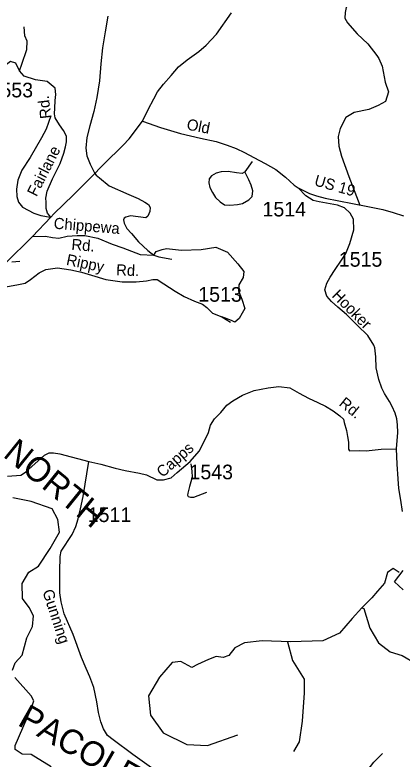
# Model space of a CAD drawing. Extents: x 990631 to 1056237, y 535999 to 585651.
# Drawn here: x 1035882 to 1039191, y 551047 to 557410 of the extents above; entities that cross this region are included whole.
import ezdxf

# ---------------------------------------------------------------- set-up
doc = ezdxf.new("R2010")
doc.units = 0
for name, color, linetype in [('Exist Hydrographic River Shore', 7, 'Continuous'), ('Exist Hydrographic River Shore Label', 7, 'Continuous'), ('Exist Road Non-System Type 51', 7, 'Continuous'), ('Exist Road Non-System Type 51 Label', 7, 'Continuous'), ('Exist Road Primary NC Attributed', 7, 'Continuous'), ('Exist Road Primary NC Structure Standard Bridge CELL', 7, 'Continuous'), ('Exist Road Secondary Type 41 Attributed', 7, 'Continuous'), ('Exist Road Secondary Type 51 Attributed', 7, 'Continuous'), ('Exist Road Secondary Type 51 Label', 7, 'Continuous'), ('Exist Road Secondary Type 51 Number Label', 7, 'Continuous')]:
    doc.layers.add(name, color=color, linetype=linetype)

msp = doc.modelspace()

# ---------------------------------------------------------------- linework, layer by layer
at = {"layer": 'Exist Hydrographic River Shore'}
for points in [[(1035860.8, 551807.2), (1035884.8, 551871.3), (1035944.8, 551935.4), (1035984.8, 552083.6), (1036032.9, 552179.7), (1036040.9, 552271.8), (1036004.9, 552343.9), (1035948.8, 552420.1), (1035944.8, 552548.2), (1036000.9, 552644.4), (1036084.9, 552696.4), (1036185, 552848.7), (1036265, 552988.9), (1036249, 553095), (1036201, 553187.1), (1036020.9, 553251.2), (1035865.5, 553280)], [(1036192.2, 550982.6), (1036020.9, 551085.9), (1035944.8, 551089.9), (1035884.8, 551129.9), (1035884.8, 551164.4), (1036024.9, 551484.8), (1036044.9, 551544.9), (1036020.9, 551589), (1035880.8, 551745.2)]]:
    msp.add_lwpolyline(points, dxfattribs=at)
at = {"layer": 'Exist Road Non-System Type 51'}
msp.add_line((1037908.7, 556156.4), (1037847.7, 556068.2), dxfattribs=at)
for points in [[(1038865.7, 557977), (1038864.4, 557873), (1038839.2, 557711.6), (1038821.1, 557648.2), (1038747.3, 557532.4), (1038713.5, 557473.5), (1038706.1, 557431.8), (1038702.5, 557381.9), (1038723.3, 557343), (1038808.2, 557248.3), (1038899.5, 557163.4), (1038974.3, 557062.9), (1038991.6, 557036.3), (1039021.5, 556971.3), (1039045.2, 556834.4)], [(1036677.7, 557398.6), (1036653.4, 557265.3), (1036631.1, 557128.1), (1036616.5, 556992.3), (1036606, 556846.7), (1036581.3, 556705.3), (1036557.5, 556583.9), (1036521.6, 556461), (1036496.4, 556361.7), (1036489.3, 556270), (1036497.2, 556205.6), (1036527, 556134.6), (1036566.4, 556053.4), (1036578.1, 556040.9)], [(1036232.8, 556730), (1036226.2, 556784.9), (1036159.3, 556839.3), (1036059, 556856), (1035962.9, 556885.3), (1035921.1, 556931.3), (1035942, 556989.9), (1035983.8, 557115.3), (1035987.9, 557186.4), (1035967, 557232.4), (1035962.9, 557307.7)], [(1035921.1, 556931.3), (1035891.8, 556998.2), (1035845.8, 557010.8), (1035799.8, 556977.3), (1035749.7, 556922.9), (1035695.3, 556835.1), (1035661.9, 556730.6)], [(1039045.2, 556834.4), (1039073.6, 556752.2), (1039048.5, 556668.6), (1038985.8, 556635.1), (1038906.4, 556601.7), (1038781, 556576.6), (1038709.6, 556533), (1038661.4, 556438.5), (1038646.1, 556370.8), (1038649.4, 556286.7), (1038672.7, 556202), (1038737, 556029.7), (1038829.1, 555784.8)], [(1036190, 556547.7), (1036148.3, 556432.9), (1036110, 556358.3), (1036012.6, 556191.2), (1035943, 556083.3), (1035908.2, 555996.4), (1035895.9, 555920.8), (1035897.8, 555856.6), (1035912.3, 555810.1), (1035948.8, 555766.9), (1036043.2, 555714), (1036104.6, 555695.9), (1036186.3, 555680.1)], [(1037847.7, 556068.2), (1037845.7, 556066.4), (1037825.2, 556053), (1037777.5, 556060.6), (1037703.7, 556070.9), (1037645.7, 556068.9), (1037601.2, 556058.1), (1037562.6, 556035.3), (1037543.6, 556008.1), (1037540.5, 555974.1), (1037549.3, 555933.7), (1037569.9, 555891.1), (1037596.6, 555848.2), (1037637.5, 555812.9), (1037674.6, 555785.6), (1037718.5, 555782.3), (1037784.9, 555790.1), (1037827.1, 555798.7), (1037882.1, 555829), (1037909.1, 555858.1), (1037916.7, 555905.9), (1037900.2, 555954.5), (1037881.5, 555999.1), (1037847.7, 556068.2)], [(1036578.1, 556040.9), (1036605.2, 556016), (1036687.1, 555947.3), (1036854.9, 555873.9), (1036935.8, 555839.5), (1036993, 555809.5), (1037024.4, 555790.5), (1037037.5, 555764), (1037036.4, 555728), (1037019, 555688.5), (1037000.7, 555675.1), (1036934.9, 555683.2), (1036871, 555691.3), (1036830.8, 555680.5), (1036816.4, 555671), (1036811.9, 555657.3), (1036817.1, 555629), (1036839.6, 555584.3), (1036878.4, 555541.1), (1036940, 555471), (1037019.7, 555396.4), (1037070.5, 555354.8), (1037112, 555341.3), (1037223.5, 555321.7)], [(1036032.9, 555514.1), (1036143.2, 555519.3), (1036203.4, 555507.5), (1036259.3, 555501.5), (1036328.4, 555517.3), (1036414.9, 555525.3), (1036479.3, 555523.3), (1036590.1, 555501.2), (1036713.7, 555449.5), (1036804.7, 555418.7), (1036951.7, 555361.3), (1037070.5, 555354.8)], [(1037070.5, 555354.8), (1037089.7, 555386.4), (1037139.8, 555403.1), (1037177.5, 555411.5), (1037307.1, 555398.9), (1037474.3, 555403.1), (1037599.7, 555424), (1037700, 555382.2), (1037787.8, 555281.9), (1037837.9, 555214.9), (1037833.8, 555164.8), (1037796.1, 555102), (1037792, 555051.8), (1037821.2, 554980.8), (1037846.3, 554901.3), (1037825.4, 554859.5), (1037800.3, 554813.5), (1037762.7, 554784.2), (1037733.4, 554796.7), (1037651.5, 554828.4)], [(1037385.5, 553571.4), (1037393.4, 553509.2), (1037397.8, 553458.9), (1037375.2, 553377.5), (1037359.4, 553322), (1037356.9, 553304.1), (1037364.4, 553291.9), (1037382.3, 553287.3), (1037412.4, 553288.3), (1037523.8, 553328.9)], [(1039165.8, 552643), (1039115.6, 552676.5), (1039065.4, 552643), (1039040.4, 552551), (1038981.8, 552484.1), (1038931.7, 552425.6), (1038873.2, 552367), (1038848.1, 552341.9), (1038864.8, 552333.6), (1038915, 552166.3), (1038990.2, 552040.8), (1039090.5, 551965.6), (1039190.8, 551932.1), (1039307.9, 551865.2)], [(1038848.1, 552341.9), (1038764.5, 552249.9), (1038655.8, 552124.5), (1038513.7, 552057.6), (1038237.8, 552049.2), (1037995.3, 552057.6), (1037844.8, 552040.8), (1037761.2, 551999), (1037711.1, 551932.1), (1037660.9, 551915.4), (1037602.4, 551923.7), (1037535.5, 551898.6), (1037443.5, 551856.8), (1037393.4, 551831.7), (1037301.4, 551881.9), (1037226.2, 551873.6), (1037117.5, 551748.1), (1037025.5, 551589.2), (1037042.2, 551421.9), (1037150.9, 551271.3), (1037351.6, 551171), (1037527.1, 551162.6), (1037786.3, 551254.6)], [(1038212.7, 552049.2), (1038254.5, 551890.3), (1038354.8, 551731.4), (1038354.8, 551614.3), (1038338.1, 551371.7), (1038313, 551196.1), (1038262.8, 551112.4)], [(1039006.9, 549724), (1039023.6, 549841.1), (1038981.8, 549908), (1038923.3, 549991.7), (1038873.2, 550050.2), (1038856.4, 550142.2), (1038881.5, 550242.6), (1038923.3, 550326.2), (1038940, 550476.8), (1038889.9, 550585.5), (1038889.9, 550677.5), (1038864.8, 550844.8), (1038873.2, 550920.1), (1038948.4, 551020.4), (1039023.6, 551095.7)]]:
    msp.add_lwpolyline(points, dxfattribs=at)
at = {"layer": 'Exist Road Primary NC Attributed'}
for points in [[(1036972.7, 556501.8), (1037022.3, 556601.1), (1037069.4, 556693.5), (1037101.8, 556753.6), (1037153.7, 556818.4), (1037218.5, 556891.4), (1037281.7, 556966.1), (1037353.4, 557025.7), (1037455, 557098.5), (1037516.3, 557151.4), (1037606, 557245.1), (1037732.7, 557428.1)], [(1036190.1, 555682.1), (1036215.7, 555708.8), (1036383.5, 555871.1), (1036533.1, 556022.2), (1036643, 556133.9), (1036808.3, 556297.7), (1036858.6, 556349.6), (1036972.7, 556501.8)], [(1035781.5, 555265), (1035803.1, 555286.2), (1036032.9, 555514.1), (1036190.1, 555682.1)]]:
    msp.add_lwpolyline(points, dxfattribs=at)
at = {"layer": 'Exist Road Primary NC Structure Standard Bridge CELL'}
msp.add_line((1035855.3, 555297.5), (1035924, 555303.5), dxfattribs=at)
at = {"layer": 'Exist Road Secondary Type 41 Attributed'}
msp.add_lwpolyline([(1035772.9, 555078.2), (1035913.5, 555105.5), (1035970.7, 555117.5), (1036015.9, 555146.8), (1036089, 555205.3), (1036147.5, 555233.2), (1036245.9, 555246.5), (1036361.5, 555231.9), (1036450.6, 555211.9), (1036538.4, 555184), (1036659.3, 555148.1), (1036798.9, 555126.8), (1036918.6, 555128.1), (1037006.3, 555137.4), (1037062.2, 555148.1), (1037096.8, 555146.8), (1037153.9, 555112.2), (1037252.3, 555047), (1037329.1, 555003.2), (1037417.8, 554963.3), (1037486.5, 554935.8), (1037522.7, 554908.3), (1037571.4, 554859.5), (1037651.5, 554828.4), (1037724.3, 554782.9)], dxfattribs=at)
at = {"layer": 'Exist Road Secondary Type 51 Attributed'}
for points in [[(1036190.1, 555682.1), (1036161.1, 555715.8), (1036148.5, 555756.3), (1036148.5, 555808.1), (1036147.1, 555844.5), (1036157.4, 555902.4), (1036202.8, 556009.1), (1036269, 556139), (1036300, 556228), (1036315.2, 556282.9), (1036323.6, 556325), (1036324.8, 556374.3), (1036297.2, 556421.2), (1036263.5, 556469.3), (1036227.4, 556530.7), (1036220.2, 556564.4), (1036223.3, 556613.5), (1036225.7, 556677.7), (1036232.8, 556730)], [(1036972.7, 556501.8), (1037127.7, 556447), (1037297.9, 556395.1), (1037469.2, 556357.1), (1037603, 556328.3), (1037696.5, 556296.6), (1037772.7, 556269.2), (1037844.7, 556234.7), (1037925.3, 556191.5), (1038021.7, 556139.7), (1038110.9, 556087.8), (1038195.7, 556023.1), (1038269.1, 555955.4), (1038303.3, 555930.5)], [(1039143.2, 553700.9), (1039155.4, 553840.8), (1039151.8, 553904.4), (1039145.7, 553957.3), (1039132.2, 554005.7), (1039105, 554063.1), (1039083.6, 554105.4), (1039041.6, 554173.4), (1039017.4, 554218.7), (1038993.2, 554292.7), (1038969.1, 554393.7), (1038965.9, 554487.3), (1038958.2, 554563.7), (1038949, 554586.1), (1038897.6, 554668.5), (1038810.5, 554753.4), (1038716.8, 554849.4), (1038640.9, 554912), (1038587.3, 554961.1), (1038549.3, 555005.8), (1038531.5, 555059.4), (1038549.3, 555115.3), (1038576.1, 555168.9), (1038618.5, 555233.6), (1038674.4, 555314.1), (1038710.1, 555369.9), (1038745.8, 555454.8), (1038779.3, 555573.2), (1038777.1, 555662.6), (1038748, 555713.9), (1038698.9, 555760.9), (1038640.3, 555783.7), (1038481.8, 555810.6), (1038430.5, 555822.8), (1038367.9, 555861.9), (1038303.3, 555930.5)], [(1038303.3, 555930.5), (1038399.2, 555882), (1038458.4, 555863.1), (1038533.2, 555844.1), (1038768.1, 555797), (1038897.9, 555771.1), (1039027.3, 555745.2), (1039115.1, 555719.3), (1039204.3, 555691.9)], [(1036515.4, 553591.2), (1036615.5, 553568.3), (1036739.5, 553533.8), (1036824.8, 553515.5), (1036946.7, 553493.1), (1037007.7, 553476.8), (1037095.1, 553436.2), (1037152, 553434.1), (1037219, 553452.4), (1037269.8, 553497.2), (1037381.6, 553592.7), (1037456.7, 553680.2), (1037501.4, 553767.6), (1037536, 553838.7), (1037554.3, 553903.8), (1037586.8, 553956.7), (1037641.6, 554011.6), (1037694.5, 554074.6), (1037745.3, 554111.2), (1037828.6, 554157.9), (1037928.1, 554198.6), (1038046, 554223), (1038137.4, 554233.2), (1038230.9, 554221), (1038311.4, 554176.2), (1038391.4, 554133.5), (1038470.7, 554096.9), (1038535.7, 554064.4), (1038602.7, 554023.8), (1038659.6, 553983.1), (1038690.1, 553954.6), (1038696.2, 553924.1), (1038717.5, 553856.9), (1038725.8, 553804.7), (1038732.3, 553758.3), (1038734.3, 553698.3), (1038742, 553684.1), (1038828.3, 553686.3), (1038885.2, 553684.2), (1039013.2, 553696.4), (1039143.2, 553700.9)], [(1035819.6, 553465.5), (1035932.2, 553474.8), (1035972.3, 553501), (1036135.8, 553646.1), (1036175.9, 553666.2), (1036212.9, 553664.6), (1036266.9, 553656.9), (1036515.4, 553591.2)], [(1039195.7, 553165.2), (1039180.6, 553261.7), (1039163.9, 553362.3), (1039156.5, 553444.5), (1039150.4, 553568.8), (1039143.2, 553700.9)], [(1037089, 550943.6), (1036889.9, 551085.9), (1036723.2, 551212), (1036672.4, 551248.7), (1036640.4, 551305.8), (1036616.1, 551364.7), (1036596.8, 551445.3), (1036581.6, 551535.8), (1036555.6, 551658.8), (1036522.5, 551749.9), (1036490.7, 551823), (1036453, 551917.4), (1036379.8, 552112.6), (1036304.7, 552289.5), (1036278.3, 552391.2), (1036266.1, 552468.4), (1036266.1, 552651.4), (1036268.1, 552779.5), (1036278.3, 552826.2), (1036371.7, 552966.5), (1036403.6, 553036.6), (1036423.7, 553102), (1036442.8, 553188.1), (1036465.2, 553291.8), (1036515.4, 553591.2)], [(1039201.6, 552493.3), (1039127.6, 552564.3), (1039199.3, 552658.7)]]:
    msp.add_lwpolyline(points, dxfattribs=at)

# ---------------------------------------------------------------- texts
at = {"layer": 'Exist Hydrographic River Shore Label'}
for s, rotation, p in [('NORTH', 321.06581, (1035772.5, 553638.4)), ('PACOLET', 330.43346, (1035896.4, 551342.1))]:
    msp.add_text(s, height=210, rotation=rotation, dxfattribs=at).set_placement(p)
at = {"layer": 'Exist Road Non-System Type 51 Label'}
for s, p in [('Chippewa', (1036211.1, 555583.1)), ('Rd.', (1036362.9, 555402.1))]:
    msp.add_text(s, height=95, rotation=355.2698, dxfattribs=at).set_placement(p)
at = {"layer": 'Exist Road Secondary Type 51 Label'}
for s, rotation, p in [('Rd.', 96.9446, (1036194.6, 556528.1)), ('Old', 348.88076, (1037344.9, 556430.7)), ('Fairlane', 62.98443, (1036066.6, 555850.3)), ('US 19', 344.08721, (1038434.5, 555953.9)), ('Rippy', 348.37155, (1036316.1, 555274)), ('Rd.', 358.07235, (1036746.4, 555183.3)), ('Hooker', 314.78993, (1038585, 555005.4)), ('Rd.', 320.9543, (1038645.1, 554076.4)), ('Capps', 41.55584, (1037144.7, 553450.4)), ('Gunning', 288.10447, (1036116.4, 552481))]:
    msp.add_text(s, height=95, rotation=rotation, dxfattribs=at).set_placement(p)
at = {"layer": 'Exist Road Secondary Type 51 Number Label'}
for s, p in [('1553', (1035665.7, 556705.2)), ('1514', (1037998.5, 555686.8)), ('1515', (1038650.6, 555257.2)), ('1513', (1037449.5, 554957.9)), ('1543', (1037374.6, 553439.8)), ('1511', (1036504.7, 553074.2))]:
    msp.add_text(s, height=125, dxfattribs=at).set_placement(p)

doc.saveas('drawing.dxf')
